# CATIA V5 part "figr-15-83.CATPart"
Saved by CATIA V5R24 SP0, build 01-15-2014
Part number: Part1
Bounding box of the stored display mesh (mm): x 0 to 27, y -46 to 46, z -30 to 30
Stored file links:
  D:\KAVITA\CATIA V5-6R2014 Project_ Kavita\CATIA V5-6R2014_partfiles\Partfiles\c15_catia_v5-6r2014_prt\figr-15-83.CATPart
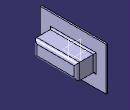
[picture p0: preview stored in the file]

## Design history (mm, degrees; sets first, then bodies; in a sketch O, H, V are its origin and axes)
SheetMetalParameters1: Thickness 2, BendRadius 4, ReliefRadialLength 1, KFactor 0.400515 {= log(min(100,max(20*SheetMetalParameters1.BendRadius,SheetMetalParameters1.Thickness)/SheetMetalParameters1.Thickness))/log(100)/2}, ReliefAxialLength 2, MinimumBendRadius 0
Body1 (main body)
  Sketch1 on yz-plane, origin (0, 0, 0), H (0, 1, 0), V (0, 0, 1)
    line L1 (46, 30) -> (46, -30)
    line L2 (46, -30) -> (-46, -30)
    line L3 (-46, -30) -> (-46, 30)
    line L4 (-46, 30) -> (46, 30)
    vertical: L1 V, L3 V
    horizontal: L2 H, L4 H
    equidistance: L1 L3 O, L2 L4 O
  Wall1: Thickness 2, Profile Sketch1, OffsetValue 0
  Sketch2 on face of Wall1, origin (2, 0, 0), H (0, 1, 0), V (0, 0, 1)
    line L1 (28, 9) -> (28, -9)
    line L2 (28, -9) -> (-28, -9)
    line L3 (-28, -9) -> (-28, 9)
    line L4 (-28, 9) -> (28, 9)
    vertical: L1 V, L3 V
    horizontal: L2 H, L4 H
    equidistance: L1 L3 O, L2 L4 O
  d_Stamp1: NewRoot_AttribNormalisation "No Standard", Stamp_FilletRadius 2, Stamp_IntersectFilletRadius 2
